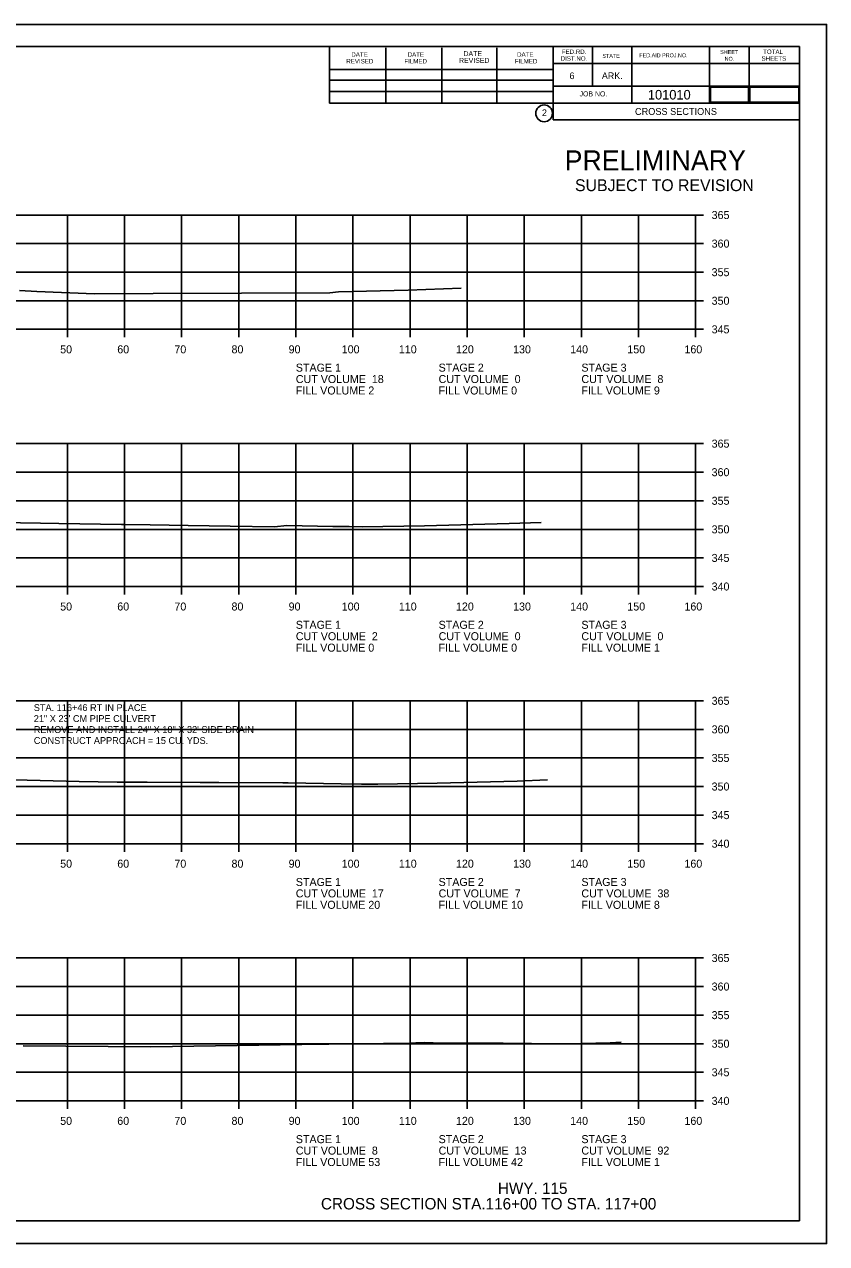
# Model space of a CAD drawing. Extents: x 1630712 to 1632516, y 782146 to 785403.
# Drawn here: x 1632375.4 to 1632515.9, y 785190 to 785403.3 of the extents above; entities that cross this region are included whole.
import ezdxf

# ---------------------------------------------------------------- set-up
doc = ezdxf.new("R2010")
doc.units = 0
for name, color, linetype in [('Page Number', 7, 'Continuous'), ('R_Axis', 7, 'Continuous'), ('R_Axis Annot', 7, 'Continuous'), ('R_Border', 7, 'Continuous'), ('R_Border Notes', 7, 'Continuous'), ('R_Border Prem', 7, 'Continuous'), ('R_Culvert Temporary Annot', 7, 'Continuous'), ('R_Draft', 7, 'Continuous'), ('R_Exist Surface', 7, 'Continuous'), ('R_Grid', 7, 'Continuous'), ('R_No Plot', 7, 'Continuous'), ('Total_Pages', 7, 'Continuous')]:
    doc.layers.add(name, color=color, linetype=linetype)

msp = doc.modelspace()

# ---------------------------------------------------------------- linework, layer by layer
at = {"layer": 'Page Number'}
msp.add_lwpolyline([(1632495.54, 785389.71), (1632502.21, 785389.71), (1632502.21, 785392.35), (1632495.54, 785392.35)], close=True, dxfattribs=at)
at = {"layer": 'R_Axis'}
for p, q in [((1632492.96, 785349.98), (1632492.96, 785369.98)), ((1632494.36, 785369.98), (1632492.96, 785369.98)), ((1632494.36, 785364.98), (1632492.96, 785364.98)), ((1632494.36, 785359.98), (1632492.96, 785359.98)), ((1632494.36, 785354.98), (1632492.96, 785354.98)), ((1632212.96, 785349.98), (1632492.96, 785349.98)), ((1632382.96, 785348.58), (1632382.96, 785349.98)), ((1632392.96, 785348.58), (1632392.96, 785349.98)), ((1632402.96, 785348.58), (1632402.96, 785349.98)), ((1632412.96, 785348.58), (1632412.96, 785349.98)), ((1632422.96, 785348.58), (1632422.96, 785349.98)), ((1632432.96, 785348.58), (1632432.96, 785349.98)), ((1632442.96, 785348.58), (1632442.96, 785349.98)), ((1632452.96, 785348.58), (1632452.96, 785349.98)), ((1632462.96, 785348.58), (1632462.96, 785349.98)), ((1632472.96, 785348.58), (1632472.96, 785349.98)), ((1632482.96, 785348.58), (1632482.96, 785349.98)), ((1632492.96, 785348.58), (1632492.96, 785349.98)), ((1632494.36, 785349.98), (1632492.96, 785349.98)), ((1632492.96, 785304.98), (1632492.96, 785329.98)), ((1632494.36, 785329.98), (1632492.96, 785329.98)), ((1632494.36, 785324.98), (1632492.96, 785324.98)), ((1632494.36, 785319.98), (1632492.96, 785319.98)), ((1632494.36, 785314.98), (1632492.96, 785314.98)), ((1632494.36, 785309.98), (1632492.96, 785309.98)), ((1632212.96, 785304.98), (1632492.96, 785304.98)), ((1632382.96, 785303.58), (1632382.96, 785304.98)), ((1632392.96, 785303.58), (1632392.96, 785304.98)), ((1632402.96, 785303.58), (1632402.96, 785304.98)), ((1632412.96, 785303.58), (1632412.96, 785304.98)), ((1632422.96, 785303.58), (1632422.96, 785304.98)), ((1632432.96, 785303.58), (1632432.96, 785304.98)), ((1632442.96, 785303.58), (1632442.96, 785304.98)), ((1632452.96, 785303.58), (1632452.96, 785304.98)), ((1632462.96, 785303.58), (1632462.96, 785304.98)), ((1632472.96, 785303.58), (1632472.96, 785304.98)), ((1632482.96, 785303.58), (1632482.96, 785304.98)), ((1632492.96, 785303.58), (1632492.96, 785304.98)), ((1632494.36, 785304.98), (1632492.96, 785304.98)), ((1632492.96, 785259.98), (1632492.96, 785284.98)), ((1632494.36, 785284.98), (1632492.96, 785284.98)), ((1632494.36, 785279.98), (1632492.96, 785279.98)), ((1632494.36, 785274.98), (1632492.96, 785274.98)), ((1632494.36, 785269.98), (1632492.96, 785269.98)), ((1632494.36, 785264.98), (1632492.96, 785264.98)), ((1632212.96, 785259.98), (1632492.96, 785259.98)), ((1632382.96, 785258.58), (1632382.96, 785259.98)), ((1632392.96, 785258.58), (1632392.96, 785259.98)), ((1632402.96, 785258.58), (1632402.96, 785259.98)), ((1632412.96, 785258.58), (1632412.96, 785259.98)), ((1632422.96, 785258.58), (1632422.96, 785259.98)), ((1632432.96, 785258.58), (1632432.96, 785259.98)), ((1632442.96, 785258.58), (1632442.96, 785259.98)), ((1632452.96, 785258.58), (1632452.96, 785259.98)), ((1632462.96, 785258.58), (1632462.96, 785259.98)), ((1632472.96, 785258.58), (1632472.96, 785259.98)), ((1632482.96, 785258.58), (1632482.96, 785259.98)), ((1632492.96, 785258.58), (1632492.96, 785259.98)), ((1632494.36, 785259.98), (1632492.96, 785259.98)), ((1632492.96, 785214.98), (1632492.96, 785239.98)), ((1632494.36, 785239.98), (1632492.96, 785239.98)), ((1632494.36, 785234.98), (1632492.96, 785234.98)), ((1632494.36, 785229.98), (1632492.96, 785229.98)), ((1632494.36, 785224.98), (1632492.96, 785224.98)), ((1632494.36, 785219.98), (1632492.96, 785219.98)), ((1632212.96, 785214.98), (1632492.96, 785214.98)), ((1632382.96, 785213.58), (1632382.96, 785214.98)), ((1632392.96, 785213.58), (1632392.96, 785214.98)), ((1632402.96, 785213.58), (1632402.96, 785214.98)), ((1632412.96, 785213.58), (1632412.96, 785214.98)), ((1632422.96, 785213.58), (1632422.96, 785214.98)), ((1632432.96, 785213.58), (1632432.96, 785214.98)), ((1632442.96, 785213.58), (1632442.96, 785214.98)), ((1632452.96, 785213.58), (1632452.96, 785214.98)), ((1632462.96, 785213.58), (1632462.96, 785214.98)), ((1632472.96, 785213.58), (1632472.96, 785214.98)), ((1632482.96, 785213.58), (1632482.96, 785214.98)), ((1632492.96, 785213.58), (1632492.96, 785214.98)), ((1632494.36, 785214.98), (1632492.96, 785214.98))]:
    msp.add_line(p, q, dxfattribs=at)
at = {"layer": 'R_Border'}
for p, q in [((1632194.96, 785399.44), (1632511.14, 785399.44)), ((1632428.88, 785389.56), (1632428.88, 785399.44)), ((1632438.74, 785389.56), (1632438.74, 785399.24)), ((1632448.5, 785389.56), (1632448.5, 785399.24)), ((1632458.18, 785389.56), (1632458.18, 785399.24)), ((1632468.04, 785399.44), (1632468.04, 785386.64)), ((1632474.88, 785399.44), (1632474.88, 785392.5)), ((1632481.82, 785399.44), (1632481.82, 785389.56)), ((1632495.4, 785399.44), (1632495.4, 785389.56)), ((1632502.34, 785399.44), (1632502.34, 785389.56)), ((1632511.14, 785193.98), (1632511.14, 785399.44)), ((1632511.14, 785396.5), (1632468.04, 785396.5)), ((1632511.14, 785396.52), (1632511.14, 785396.52)), ((1632428.88, 785395.42), (1632468.04, 785395.42)), ((1632428.88, 785393.56), (1632468.04, 785393.56)), ((1632511.14, 785392.5), (1632468.04, 785392.5)), ((1632471, 785392.5), (1632511.14, 785392.5)), ((1632428.88, 785389.56), (1632428.88, 785391.62)), ((1632428.88, 785391.62), (1632468.04, 785391.62)), ((1632511.14, 785389.56), (1632428.88, 785389.56)), ((1632468.04, 785386.64), (1632511.14, 785386.64)), ((1632511.14, 785193.98), (1632194.96, 785193.98))]:
    msp.add_line(p, q, dxfattribs=at)
msp.add_circle((1632466.43, 785387.78), 1.47, dxfattribs=at)
at = {"layer": 'R_Exist Surface'}
for points in [[(1632374.61, 785356.75), (1632377.59, 785356.62), (1632387.7, 785356.21), (1632397.98, 785356.25), (1632428.89, 785356.39), (1632430.41, 785356.53), (1632442.63, 785356.85), (1632451.91, 785357.18)], [(1632367.65, 785316.25), (1632378.23, 785316.07), (1632381.45, 785315.98), (1632392.45, 785315.83), (1632393.09, 785315.82), (1632397.47, 785315.8), (1632404.11, 785315.66), (1632411.46, 785315.56), (1632419.2, 785315.43), (1632421.39, 785315.63), (1632429.47, 785315.48), (1632432.28, 785315.46), (1632434.57, 785315.44), (1632445.5, 785315.62), (1632460.31, 785316), (1632465.91, 785316.2)], [(1632373.64, 785271.16), (1632385.05, 785270.84), (1632391.69, 785270.74), (1632396.94, 785270.72), (1632406.22, 785270.68), (1632409.5, 785270.66), (1632420.68, 785270.61), (1632421.61, 785270.62), (1632430.88, 785270.45), (1632434.44, 785270.42), (1632437.33, 785270.4), (1632447.69, 785270.57), (1632461.73, 785270.94), (1632467.03, 785271.13)], [(1632375.2, 785224.6), (1632397.58, 785224.46), (1632423.99, 785224.86), (1632443.02, 785225.09), (1632443.95, 785225.15), (1632445.52, 785225.17), (1632447.03, 785225.14), (1632459.25, 785225.05), (1632469.16, 785224.97), (1632472.91, 785225.03), (1632477.99, 785225.16), (1632479.92, 785225.23)]]:
    msp.add_lwpolyline(points, dxfattribs=at)
at = {"layer": 'R_Grid'}
for p, q in [((1632212.96, 785369.98), (1632492.96, 785369.98)), ((1632382.96, 785349.98), (1632382.96, 785369.98)), ((1632392.96, 785349.98), (1632392.96, 785369.98)), ((1632402.96, 785349.98), (1632402.96, 785369.98)), ((1632412.96, 785349.98), (1632412.96, 785369.98)), ((1632422.96, 785349.98), (1632422.96, 785369.98)), ((1632432.96, 785349.98), (1632432.96, 785369.98)), ((1632442.96, 785349.98), (1632442.96, 785369.98)), ((1632452.96, 785349.98), (1632452.96, 785369.98)), ((1632462.96, 785349.98), (1632462.96, 785369.98)), ((1632472.96, 785349.98), (1632472.96, 785369.98)), ((1632482.96, 785349.98), (1632482.96, 785369.98)), ((1632492.96, 785349.98), (1632492.96, 785369.98)), ((1632212.96, 785364.98), (1632492.96, 785364.98)), ((1632212.96, 785359.98), (1632492.96, 785359.98)), ((1632212.96, 785354.98), (1632492.96, 785354.98)), ((1632212.96, 785349.98), (1632492.96, 785349.98)), ((1632212.96, 785329.98), (1632492.96, 785329.98)), ((1632382.96, 785304.98), (1632382.96, 785329.98)), ((1632392.96, 785304.98), (1632392.96, 785329.98)), ((1632402.96, 785304.98), (1632402.96, 785329.98)), ((1632412.96, 785304.98), (1632412.96, 785329.98)), ((1632422.96, 785304.98), (1632422.96, 785329.98)), ((1632432.96, 785304.98), (1632432.96, 785329.98)), ((1632442.96, 785304.98), (1632442.96, 785329.98)), ((1632452.96, 785304.98), (1632452.96, 785329.98)), ((1632462.96, 785304.98), (1632462.96, 785329.98)), ((1632472.96, 785304.98), (1632472.96, 785329.98)), ((1632482.96, 785304.98), (1632482.96, 785329.98)), ((1632492.96, 785304.98), (1632492.96, 785329.98)), ((1632212.96, 785324.98), (1632492.96, 785324.98)), ((1632212.96, 785319.98), (1632492.96, 785319.98)), ((1632212.96, 785314.98), (1632492.96, 785314.98)), ((1632212.96, 785309.98), (1632492.96, 785309.98)), ((1632212.96, 785304.98), (1632492.96, 785304.98)), ((1632212.96, 785284.98), (1632492.96, 785284.98)), ((1632382.96, 785259.98), (1632382.96, 785284.98)), ((1632392.96, 785259.98), (1632392.96, 785284.98)), ((1632402.96, 785259.98), (1632402.96, 785284.98)), ((1632412.96, 785259.98), (1632412.96, 785284.98)), ((1632422.96, 785259.98), (1632422.96, 785284.98)), ((1632432.96, 785259.98), (1632432.96, 785284.98)), ((1632442.96, 785259.98), (1632442.96, 785284.98)), ((1632452.96, 785259.98), (1632452.96, 785284.98)), ((1632462.96, 785259.98), (1632462.96, 785284.98)), ((1632472.96, 785259.98), (1632472.96, 785284.98)), ((1632482.96, 785259.98), (1632482.96, 785284.98)), ((1632492.96, 785259.98), (1632492.96, 785284.98)), ((1632212.96, 785279.98), (1632492.96, 785279.98)), ((1632212.96, 785274.98), (1632492.96, 785274.98)), ((1632212.96, 785269.98), (1632492.96, 785269.98)), ((1632212.96, 785264.98), (1632492.96, 785264.98)), ((1632212.96, 785259.98), (1632492.96, 785259.98)), ((1632212.96, 785239.98), (1632492.96, 785239.98)), ((1632382.96, 785214.98), (1632382.96, 785239.98)), ((1632392.96, 785214.98), (1632392.96, 785239.98)), ((1632402.96, 785214.98), (1632402.96, 785239.98)), ((1632412.96, 785214.98), (1632412.96, 785239.98)), ((1632422.96, 785214.98), (1632422.96, 785239.98)), ((1632432.96, 785214.98), (1632432.96, 785239.98)), ((1632442.96, 785214.98), (1632442.96, 785239.98)), ((1632452.96, 785214.98), (1632452.96, 785239.98)), ((1632462.96, 785214.98), (1632462.96, 785239.98)), ((1632472.96, 785214.98), (1632472.96, 785239.98)), ((1632482.96, 785214.98), (1632482.96, 785239.98)), ((1632492.96, 785214.98), (1632492.96, 785239.98)), ((1632212.96, 785234.98), (1632492.96, 785234.98)), ((1632212.96, 785229.98), (1632492.96, 785229.98)), ((1632212.96, 785224.98), (1632492.96, 785224.98)), ((1632212.96, 785219.98), (1632492.96, 785219.98)), ((1632212.96, 785214.98), (1632492.96, 785214.98))]:
    msp.add_line(p, q, dxfattribs=at)
at = {"layer": 'R_No Plot'}
for p, q in [((1632182.56, 785403.34), (1632515.9, 785403.34)), ((1632182.56, 785190), (1632515.9, 785190))]:
    msp.add_line(p, q, dxfattribs=at)
msp.add_lwpolyline([(1632182.56, 785403.34), (1632515.9, 785403.34), (1632515.9, 785190), (1632182.56, 785190)], close=True, dxfattribs=at)
at = {"layer": 'Total_Pages'}
msp.add_lwpolyline([(1632502.44, 785389.71), (1632511.05, 785389.71), (1632511.05, 785392.35), (1632502.44, 785392.35)], close=True, dxfattribs=at)

# ---------------------------------------------------------------- texts
at = {"layer": 'R_Axis Annot'}
for s, p in [('365', (1632495.76, 785369.28)), ('360', (1632495.76, 785364.28)), ('355', (1632495.76, 785359.28)), ('350', (1632495.76, 785354.28)), ('345', (1632495.76, 785349.28)), ('50', (1632381.7, 785345.78)), ('60', (1632391.7, 785345.78)), ('70', (1632401.7, 785345.78)), ('80', (1632411.7, 785345.78)), ('90', (1632421.7, 785345.78)), ('100', (1632431, 785345.78)), ('110', (1632441, 785345.78)), ('120', (1632451, 785345.78)), ('130', (1632461, 785345.78)), ('140', (1632471, 785345.78)), ('150', (1632481, 785345.78)), ('160', (1632491, 785345.78)), ('STAGE 1', (1632422.96, 785342.58)), ('STAGE 2', (1632447.96, 785342.58)), ('STAGE 3', (1632472.96, 785342.58)), ('CUT VOLUME  18', (1632422.96, 785340.58)), ('CUT VOLUME  0', (1632447.96, 785340.58)), ('CUT VOLUME  8', (1632472.96, 785340.58)), ('FILL VOLUME 2', (1632422.96, 785338.58)), ('FILL VOLUME 0', (1632447.96, 785338.58)), ('FILL VOLUME 9', (1632472.96, 785338.58)), ('365', (1632495.76, 785329.28)), ('360', (1632495.76, 785324.28)), ('355', (1632495.76, 785319.28)), ('350', (1632495.76, 785314.28)), ('345', (1632495.76, 785309.28)), ('340', (1632495.76, 785304.28)), ('50', (1632381.7, 785300.78)), ('60', (1632391.7, 785300.78)), ('70', (1632401.7, 785300.78)), ('80', (1632411.7, 785300.78)), ('90', (1632421.7, 785300.78)), ('100', (1632431, 785300.78)), ('110', (1632441, 785300.78)), ('120', (1632451, 785300.78)), ('130', (1632461, 785300.78)), ('140', (1632471, 785300.78)), ('150', (1632481, 785300.78)), ('160', (1632491, 785300.78)), ('STAGE 1', (1632422.96, 785297.58)), ('STAGE 2', (1632447.96, 785297.58)), ('STAGE 3', (1632472.96, 785297.58)), ('CUT VOLUME  2', (1632422.96, 785295.58)), ('CUT VOLUME  0', (1632447.96, 785295.58)), ('CUT VOLUME  0', (1632472.96, 785295.58)), ('FILL VOLUME 0', (1632422.96, 785293.58)), ('FILL VOLUME 0', (1632447.96, 785293.58)), ('FILL VOLUME 1', (1632472.96, 785293.58)), ('365', (1632495.76, 785284.28)), ('360', (1632495.76, 785279.28)), ('355', (1632495.76, 785274.28)), ('350', (1632495.76, 785269.28)), ('345', (1632495.76, 785264.28)), ('340', (1632495.76, 785259.28)), ('50', (1632381.7, 785255.78)), ('60', (1632391.7, 785255.78)), ('70', (1632401.7, 785255.78)), ('80', (1632411.7, 785255.78)), ('90', (1632421.7, 785255.78)), ('100', (1632431, 785255.78)), ('110', (1632441, 785255.78)), ('120', (1632451, 785255.78)), ('130', (1632461, 785255.78)), ('140', (1632471, 785255.78)), ('150', (1632481, 785255.78)), ('160', (1632491, 785255.78)), ('STAGE 1', (1632422.96, 785252.58)), ('STAGE 2', (1632447.96, 785252.58)), ('STAGE 3', (1632472.96, 785252.58)), ('CUT VOLUME  17', (1632422.96, 785250.58)), ('CUT VOLUME  7', (1632447.96, 785250.58)), ('CUT VOLUME  38', (1632472.96, 785250.58)), ('FILL VOLUME 20', (1632422.96, 785248.58)), ('FILL VOLUME 10', (1632447.96, 785248.58)), ('FILL VOLUME 8', (1632472.96, 785248.58)), ('365', (1632495.76, 785239.28)), ('360', (1632495.76, 785234.28)), ('355', (1632495.76, 785229.28)), ('350', (1632495.76, 785224.28)), ('345', (1632495.76, 785219.28)), ('340', (1632495.76, 785214.28)), ('50', (1632381.7, 785210.78)), ('60', (1632391.7, 785210.78)), ('70', (1632401.7, 785210.78)), ('80', (1632411.7, 785210.78)), ('90', (1632421.7, 785210.78)), ('100', (1632431, 785210.78)), ('110', (1632441, 785210.78)), ('120', (1632451, 785210.78)), ('130', (1632461, 785210.78)), ('140', (1632471, 785210.78)), ('150', (1632481, 785210.78)), ('160', (1632491, 785210.78)), ('STAGE 1', (1632422.96, 785207.58)), ('STAGE 2', (1632447.96, 785207.58)), ('STAGE 3', (1632472.96, 785207.58)), ('CUT VOLUME  8', (1632422.96, 785205.58)), ('CUT VOLUME  13', (1632447.96, 785205.58)), ('CUT VOLUME  92', (1632472.96, 785205.58)), ('FILL VOLUME 53', (1632422.96, 785203.58)), ('FILL VOLUME 42', (1632447.96, 785203.58)), ('FILL VOLUME 1', (1632472.96, 785203.58))]:
    msp.add_text(s, height=1.4, dxfattribs=at).set_placement(p)
at = {"layer": 'R_Border'}
for s, height, p in [('DATE', 0.782, (1632432.68, 785397.68)), ('DATE', 0.782, (1632442.54, 785397.68)), ('DATE', 0.879, (1632452.32, 785397.78)), ('DATE', 0.782, (1632461.7, 785397.68)), ('FED.RD.', 0.782, (1632469.52, 785398.16)), ('STATE', 0.684, (1632476.64, 785397.48)), ('FED.AID PROJ.NO.', 0.684, (1632483.1, 785397.58)), ('SHEET', 0.684, (1632497.26, 785398.16)), ('TOTAL', 0.782, (1632504.78, 785398.16)), ('REVISED', 0.782, (1632431.8, 785396.5)), ('FILMED', 0.782, (1632441.96, 785396.5)), ('REVISED', 0.879, (1632451.54, 785396.6)), ('FILMED', 0.782, (1632461.3, 785396.5)), ('DIST.NO.', 0.782, (1632469.32, 785396.98)), ('NO.', 0.684, (1632498.04, 785396.98)), ('SHEETS', 0.782, (1632504.5, 785396.98)), ('6', 1.17, (1632470.88, 785393.76)), ('ARK.', 1.172, (1632476.54, 785393.76)), ('JOB NO.', 0.879, (1632472.64, 785390.74)), ('2', 1.17, (1632466.05, 785387.29))]:
    msp.add_text(s, height=height, rotation=360, dxfattribs=at).set_placement(p)
at = {"layer": 'R_Border Notes'}
for s, height, p in [('101010', 1.68, (1632484.6, 785390.19)), ('CROSS SECTIONS', 1.2, (1632482.34, 785387.5))]:
    msp.add_text(s, height=height, dxfattribs=at).set_placement(p)
at = {"layer": 'R_Border Prem'}
for s, height, p in [('PRELIMINARY', 3.5, (1632470.03, 785377.79)), ('SUBJECT TO REVISION', 2.0751, (1632471.84, 785374.16))]:
    msp.add_text(s, height=height, rotation=360, dxfattribs=at).set_placement(p)
at = {"layer": 'R_Culvert Temporary Annot'}
for s, p in [('STA. 116+46 RT IN PLACE', (1632377.08, 785283.19)), ('21" X 23\' CM PIPE CULVERT', (1632377.08, 785281.27)), ('CONSTRUCT APPROACH = 15 CU. YDS.', (1632377.08, 785277.43)), ('REMOVE AND INSTALL 24" X 18" X 32\' SIDE DRAIN', (1632377.08, 785279.35))]:
    msp.add_text(s, height=1.2, dxfattribs=at).set_placement(p)
at = {"layer": 'R_Draft'}
for s, p in [('HWY. 115', (1632458.34, 785198.69)), ('CROSS SECTION STA.116+00 TO STA. 117+00', (1632427.36, 785195.98))]:
    msp.add_text(s, height=2, dxfattribs=at).set_placement(p)

doc.saveas('drawing.dxf')
